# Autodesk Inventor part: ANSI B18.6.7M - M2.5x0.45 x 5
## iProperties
Comments: To add or edit properties for Autodesk Inventor files, use iProperties.
Created: 2004-07
Part Number: ANSI B18.6.7M - M2.5x0.45 x 5
Vendor: Autodesk Inc.
Document SubType Name: Modeling
Designer: John Blackburn
Material: Default
Description: Slotted Pan Head Machine Screw (Regular Thread - Metric)
Standard: ANSI B18.6.7M
Alert: To add or edit properties for Autodesk Inventor files, use iProperties.
Control State: 0
Master: False
Checked Out: False
Shininess: 64.0
Length Units: 11269
Angle Units: 11279
Time Units: 11290
Mass Units: 11283
Length Display Precision: 3
Angle Display Precision: 2
Compacted: True
EGR: 1
Classification: un/spsc 31161501
Density: 0.0
Volumn: 0.0
Area: 0.0
PropertySet Name: Model Information
Author: John Blackburn
Revision Number: 8
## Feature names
1. Body [Revolution]
2. Fillet1
3. Slot [Extrusion]
4. Chamfer1
